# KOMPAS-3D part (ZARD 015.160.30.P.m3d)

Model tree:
1. Плоскость XY
2. Плоскость ZX
3. Плоскость ZY
4. Ось X
5. Ось Y
6. Ось Z
7. Начало координат
8. Смещенная плоскость:2
     Расстояние = 57.5
9. Смещенная плоскость:3
     Расстояние = 89
10. Смещенная плоскость:4
     Расстояние = 89
11. Булева операция:1
12. Булева операция:2
13. Булева операция:3
14. Булева операция:4
15. Булева операция:5
16. Булева операция:6
